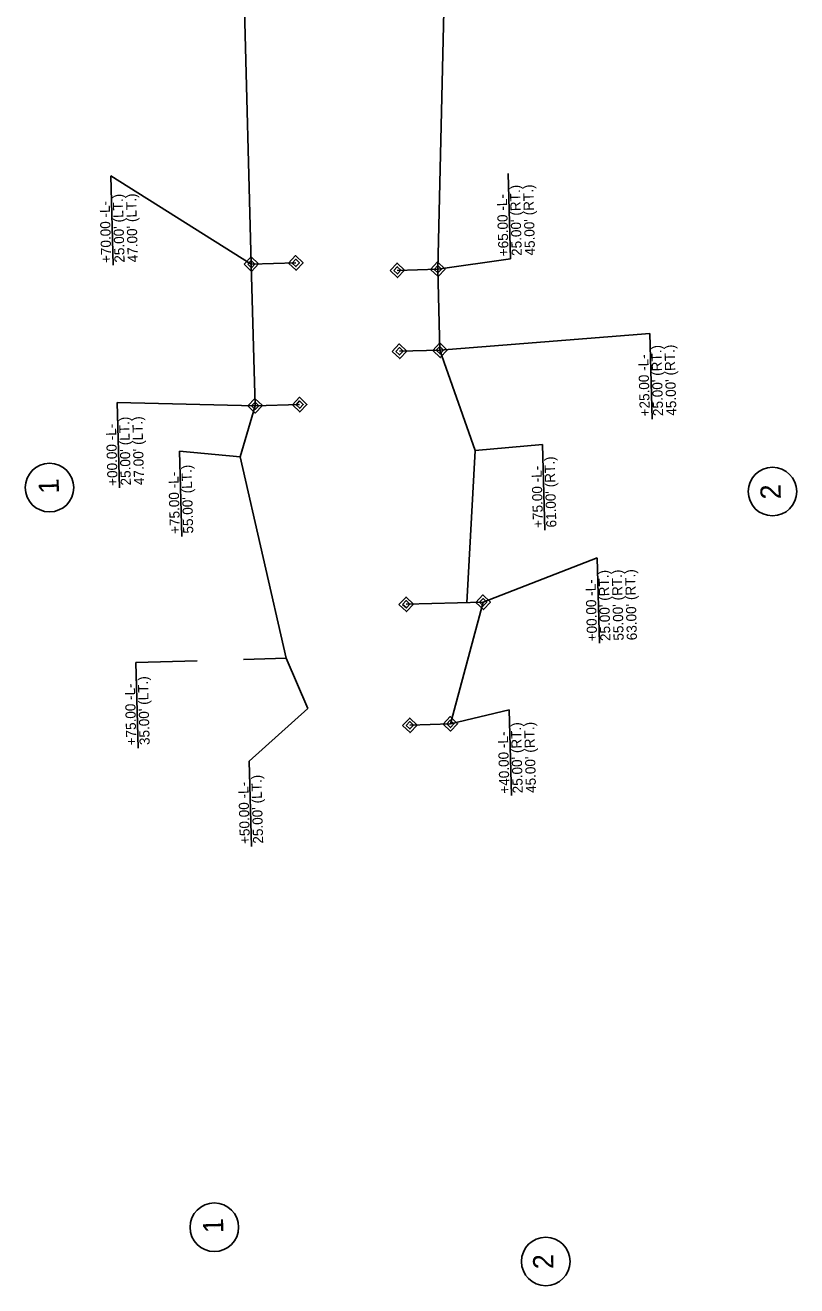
# Model space of a CAD drawing. Extents: x 1835710 to 1836442, y 994022 to 995358.
# Drawn here: x 1835729 to 1836110, y 994022 to 994644 of the extents above; entities that cross this region are included whole.
import ezdxf

# ---------------------------------------------------------------- set-up
doc = ezdxf.new("R2010")
doc.units = 0
for name, color, linetype in [('Prop Easement Construction', 7, 'Continuous'), ('Prop Easement Construction Station Offsets', 7, 'Continuous'), ('Prop Easement Permanent Drainage', 7, 'Continuous'), ('Prop Easement Permanent Drainage Station Offsets', 7, 'Continuous'), ('Prop Parcel Number CELL', 7, 'Continuous'), ('Prop ROW Marker CELL', 7, 'Continuous'), ('Prop ROW Permanent Easement CELL', 7, 'Continuous'), ('Prop ROW Text', 7, 'Continuous')]:
    doc.layers.add(name, color=color, linetype=linetype)

msp = doc.modelspace()

# ---------------------------------------------------------------- linework, layer by layer
at = {"layer": 'Prop Easement Construction'}
for p, q in [((1835841.09, 994526.23), (1835837.48, 994661.18)), ((1835933.19, 994523.7), (1835936.44, 994663.83)), ((1835951.59, 994434.16), (1835934.26, 994483.71)), ((1835835.63, 994431.05), (1835842.96, 994456.26)), ((1835858.31, 994331.57), (1835835.63, 994431.05)), ((1835947.6, 994359.02), (1835951.59, 994434.16)), ((1835869.08, 994306.74), (1835858.31, 994331.57))]:
    msp.add_line(p, q, dxfattribs=at)
at = {"layer": 'Prop Easement Construction Station Offsets'}
for p, q in [((1835984.9, 994437.09), (1835951.59, 994434.16)), ((1835986.05, 994394.88), (1835984.9, 994437.09)), ((1835806.73, 994391.68), (1835805.58, 994433.89)), ((1835805.58, 994433.89), (1835835.63, 994431.05)), ((1835784.06, 994329.43), (1835814.28, 994330.3)), ((1835785.21, 994287.23), (1835784.06, 994329.43)), ((1835837.16, 994330.96), (1835858.31, 994331.57)), ((1835840.1, 994280.74), (1835869.08, 994306.74)), ((1835841.25, 994238.54), (1835840.1, 994280.74))]:
    msp.add_line(p, q, dxfattribs=at)
at = {"layer": 'Prop Easement Permanent Drainage'}
for p, q in [((1835863.08, 994526.82), (1835841.09, 994526.23)), ((1835842.96, 994456.26), (1835841.09, 994526.23)), ((1835933.19, 994523.7), (1835913.2, 994523.16)), ((1835934.26, 994483.71), (1835933.19, 994523.7)), ((1835934.26, 994483.71), (1835914.27, 994483.18)), ((1835864.95, 994456.85), (1835842.96, 994456.26)), ((1835955.6, 994359.24), (1835917.61, 994358.22)), ((1835939.38, 994299.17), (1835955.6, 994359.24)), ((1835919.39, 994298.46), (1835939.38, 994299.17))]:
    msp.add_line(p, q, dxfattribs=at)
at = {"layer": 'Prop Easement Permanent Drainage Station Offsets'}
for p, q in [((1835772.89, 994525.79), (1835771.69, 994569.85)), ((1835771.69, 994569.85), (1835841.09, 994526.23)), ((1835969.16, 994528.81), (1835968.01, 994571.01)), ((1835969.16, 994528.81), (1835933.19, 994523.7)), ((1836037.83, 994491.91), (1835934.26, 994483.71)), ((1836038.98, 994449.71), (1836037.83, 994491.91)), ((1835776, 994415.74), (1835774.85, 994457.94)), ((1835774.85, 994457.94), (1835842.96, 994456.26)), ((1836011.89, 994381.19), (1835955.6, 994359.24)), ((1836013.04, 994338.99), (1836011.89, 994381.19)), ((1835968.44, 994306.04), (1835939.38, 994299.17)), ((1835969.6, 994263.83), (1835968.44, 994306.04))]:
    msp.add_line(p, q, dxfattribs=at)
at = {"layer": 'Prop Parcel Number CELL'}
for p, q in [((1835741.42, 994415.86), (1835741.42, 994415.86)), ((1836098.48, 994413.92), (1836098.48, 994413.92)), ((1835822.81, 994050.55), (1835822.81, 994050.55)), ((1835986.52, 994033.64), (1835986.52, 994033.64))]:
    msp.add_line(p, q, dxfattribs=at)
for centre in [(1835741.42, 994415.86), (1836098.48, 994413.92), (1835822.81, 994050.55), (1835986.52, 994033.64)]:
    msp.add_circle(centre, 12, dxfattribs=at)
at = {"layer": 'Prop ROW Marker CELL'}
for p, q in [((1835841.09, 994526.23), (1835841.09, 994526.23)), ((1835863.08, 994526.82), (1835863.08, 994526.82)), ((1835913.2, 994523.16), (1835913.2, 994523.16)), ((1835933.19, 994523.7), (1835933.19, 994523.7)), ((1835914.27, 994483.18), (1835914.27, 994483.18)), ((1835934.26, 994483.71), (1835934.26, 994483.71)), ((1835842.96, 994456.26), (1835842.96, 994456.26)), ((1835864.95, 994456.85), (1835864.95, 994456.85)), ((1835917.61, 994358.22), (1835917.61, 994358.22)), ((1835955.6, 994359.24), (1835955.6, 994359.24)), ((1835919.39, 994298.46), (1835919.39, 994298.46)), ((1835939.38, 994299.17), (1835939.38, 994299.17))]:
    msp.add_line(p, q, dxfattribs=at)
at = {"layer": 'Prop ROW Permanent Easement CELL'}
for points in [[(1835837.49, 994526.14), (1835840.99, 994529.83), (1835844.69, 994526.33), (1835841.19, 994522.63)], [(1835839.29, 994526.18), (1835841.04, 994528.03), (1835842.89, 994526.28), (1835841.14, 994524.43)], [(1835859.48, 994526.72), (1835862.98, 994530.42), (1835866.68, 994526.92), (1835863.18, 994523.22)], [(1835861.28, 994526.77), (1835863.03, 994528.62), (1835864.88, 994526.87), (1835863.13, 994525.02)], [(1835909.6, 994523.06), (1835913.1, 994526.76), (1835916.79, 994523.26), (1835913.3, 994519.56)], [(1835911.4, 994523.11), (1835913.15, 994524.96), (1835915, 994523.21), (1835913.25, 994521.36)], [(1835929.59, 994523.6), (1835933.09, 994527.3), (1835936.79, 994523.8), (1835933.29, 994520.1)], [(1835931.39, 994523.65), (1835933.14, 994525.5), (1835934.99, 994523.75), (1835933.24, 994521.9)], [(1835910.67, 994483.08), (1835914.17, 994486.78), (1835917.87, 994483.28), (1835914.37, 994479.58)], [(1835912.47, 994483.13), (1835914.22, 994484.98), (1835916.07, 994483.23), (1835914.32, 994481.38)], [(1835930.66, 994483.61), (1835934.16, 994487.31), (1835937.86, 994483.81), (1835934.36, 994480.11)], [(1835932.46, 994483.66), (1835934.21, 994485.51), (1835936.06, 994483.76), (1835934.31, 994481.91)], [(1835839.36, 994456.16), (1835842.86, 994459.86), (1835846.56, 994456.36), (1835843.06, 994452.66)], [(1835861.36, 994456.75), (1835864.86, 994460.45), (1835868.55, 994456.95), (1835865.05, 994453.25)], [(1835841.16, 994456.21), (1835842.91, 994458.06), (1835844.76, 994456.31), (1835843.01, 994454.46)], [(1835863.16, 994456.8), (1835864.91, 994458.65), (1835866.75, 994456.9), (1835865, 994455.05)], [(1835914.02, 994358.12), (1835917.52, 994361.82), (1835921.21, 994358.32), (1835917.71, 994354.62)], [(1835915.81, 994358.17), (1835917.56, 994360.02), (1835919.41, 994358.27), (1835917.66, 994356.42)], [(1835952, 994359.14), (1835955.5, 994362.84), (1835959.2, 994359.34), (1835955.7, 994355.64)], [(1835953.8, 994359.19), (1835955.55, 994361.04), (1835957.4, 994359.29), (1835955.65, 994357.44)], [(1835915.79, 994298.36), (1835919.3, 994302.06), (1835922.99, 994298.56), (1835919.49, 994294.86)], [(1835917.59, 994298.41), (1835919.34, 994300.26), (1835921.19, 994298.51), (1835919.44, 994296.66)], [(1835935.78, 994299.07), (1835939.28, 994302.76), (1835942.98, 994299.26), (1835939.48, 994295.57)], [(1835937.58, 994299.12), (1835939.33, 994300.96), (1835941.18, 994299.21), (1835939.43, 994297.37)]]:
    msp.add_lwpolyline(points, close=True, dxfattribs=at)

# ---------------------------------------------------------------- texts
at = {"layer": 'Prop Easement Construction Station Offsets'}
for s, p in [("61.00' (RT.)", (1835991.79, 994396.21)), ('+75.00 -L-', (1835805.9, 994393.05)), ("55.00' (LT.)", (1835812.45, 994393.22)), ('+75.00 -L-', (1835985.23, 994396.03)), ('+75.00 -L-', (1835784.37, 994288.59)), ("35.00' (LT.)", (1835790.93, 994288.77)), ("25.00' (LT.)", (1835846.97, 994240.08)), ('+50.00 -L-', (1835840.42, 994239.9))]:
    msp.add_text(s, height=5, rotation=91.56434, dxfattribs=at).set_placement(p)
at = {"layer": 'Prop Easement Permanent Drainage Station Offsets'}
for s, p in [("45.00' (RT.)", (1835981.25, 994530.54)), ("25.00' (LT.)", (1835778.53, 994527.02)), ("47.00' (LT.)", (1835785.08, 994527.2)), ('+65.00 -L-', (1835968.14, 994530.18)), ("25.00' (RT.)", (1835974.7, 994530.36)), ('+70.00 -L-', (1835771.98, 994526.84)), ("25.00' (RT.)", (1836044.51, 994451.26)), ("45.00' (RT.)", (1836051.06, 994451.44)), ('+25.00 -L-', (1836037.96, 994451.08)), ('+00.00 -L-', (1835775.09, 994416.79)), ("25.00' (LT.)", (1835781.64, 994416.97)), ("47.00' (LT.)", (1835788.19, 994417.15)), ("25.00' (RT.)", (1836018.46, 994340.16)), ("55.00' (RT.)", (1836025.01, 994340.34)), ("63.00' (RT.)", (1836031.56, 994340.52)), ('+00.00 -L-', (1836011.91, 994339.99)), ("25.00' (RT.)", (1835975.19, 994264.94)), ("45.00' (RT.)", (1835981.74, 994265.12)), ('+40.00 -L-', (1835968.64, 994264.76))]:
    msp.add_text(s, height=5, rotation=91.56434, dxfattribs=at).set_placement(p)
at = {"layer": 'Prop ROW Text'}
for s, p in [('1', (1835746.13, 994412.94)), ('2', (1836102.64, 994410.17)), ('1', (1835827.32, 994047.76)), ('2', (1835990.35, 994030))]:
    msp.add_text(s, height=10, rotation=91.56434, dxfattribs=at).set_placement(p)

doc.saveas('drawing.dxf')
